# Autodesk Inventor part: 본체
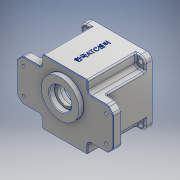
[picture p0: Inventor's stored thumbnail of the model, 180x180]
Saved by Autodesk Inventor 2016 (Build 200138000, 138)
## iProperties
Created: 2017-01
Part Number: 본체
Material: 알루미늄 6061
Document SubType Name: Modeling
Designer: Owner
Mass: 876.605 g
Surface Area: 765.17 cm^2
Volume: 324.669 cm^3
Density: 2.7 g/cm^3
Appearance: 알루미늄 - 평지
Author: Owner
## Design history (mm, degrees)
sketch "스케치1"
  geometry: L1 (47, -47)-(-47, -47); L2 (-47, -47)-(-47, 47); L3 (-47, 47)-(47, 47); L4 (47, 47)-(47, -47); L5 (47, -47)-(-47, 47); L6 (-47, -47)-(47, 47); 1 further point
  constraints: 12 end point, 2 midpoint, 2 parallel, 1 horizontal, 1 perpendicular
  dimensions: "d0" = 94 distance of L2.end L3.end; "d1" = 94 distance of L1.end L2.end
extrude "돌출1" new body sketch "스케치1" distance "d2" = 10; taper "d3" = 0 deg
sketch "스케치2"
  geometry: L1 (-33, -47)-(33, -47); L2 (33, 47)-(-33, 47); L3 (-33, -47)-(33, 47); L4 (33, -47)-(-33, 47); L5 (47, -30)-(47, 30); L6 (-47, 30)-(-47, -30); L7 (-47, -30)-(47, 30); L8 (47, -30)-(-47, 30); L9 (47, 30)-(33, 30); L10 (-33, 30)-(-47, 30); L11 (33, -47)-(33, -30); L12 (33, 30)-(33, 47); L13 (-33, 47)-(-33, 30); L14 (-33, -30)-(-33, -47); L15 (-47, -30)-(-33, -30); L16 (33, -30)-(47, -30); 9 further points
  constraints: 32 end point, 12 midpoint, 10 parallel, 4 perpendicular, 3 horizontal, 2 horizontal alignment, 2 vertical alignment
  dimensions: "d4" = 66 distance of L2.end L2.start; "d5" = 94 distance of L2.start L1.end; "d6" = 94 distance of L6.start L5.end; "d7" = 60 distance of L5.end L5.start
extrude "돌출2" join sketch "스케치2" distance "d8" = 70; taper "d9" = 0 deg
sketch "스케치3"
  geometry: L1 (70, -30)-(70, 30); L2 (-70, 30)-(-70, -30); L3 (-70, -30)-(70, 30); L4 (70, -30)-(-70, 30); L5 (33, -30)-(33, -47) reference; L6 (-33, 47)-(33, 47); L7 (33, -47)-(-33, -47); L8 (-33, 47)-(33, -47); L9 (33, 47)-(-33, -47); L10 (70, 30)-(33, 30); L11 (-33, 30)-(-70, 30); L12 (33, 47)-(33, 30); L13 (33, -30)-(33, -47); L14 (-70, -30)-(-33, -30); L15 (33, -30)-(70, -30); L16 (-33, -47)-(-33, -30); L17 (-33, 30)-(-33, 47); 9 further points
  constraints: 32 end point, 12 midpoint, 10 parallel, 4 perpendicular, 3 horizontal, 2 horizontal alignment, 2 vertical alignment
  dimensions: "d10" = 140 distance of L2.start L1.end; "d11" = 60 distance of L1.end L1.start
extrude "돌출3" join sketch "스케치3" distance "d12" = 13; taper "d13" = 0 deg
sketch "스케치5"
  geometry: 2 further points
  constraints: 1 coincident
hole "구멍1" sketch "스케치5" at (0, 0) diameter "d14" = 80; stored, may be unused: countersink angle "d18" = 90 deg, drill point angle "d20" = 0 deg; dims "d15" = 6, "d16" = 86, "d17" = 9, "d19" = 71
sketch "스케치6"
  geometry: C1 r 21 at (0, -11); 1 further point
  constraints: 1 centre point, 1 vertical alignment
  dimensions: "d21" = 42 diameter of C1; "d22" = 11 distance of point (0, 0) C1.centre
extrude "돌출4" join sketch "스케치6" distance "d23" = 7; taper "d24" = 0 deg
sketch "스케치7"
  geometry: C1 r 15 at (0, 20); 1 further point
  constraints: 1 centre point, 1 vertical alignment
  dimensions: "d25" = 30 diameter of C1; "d26" = 20 distance of point (0, 0) C1.centre
extrude "돌출5" join sketch "스케치7" distance "d27" = 7; taper "d28" = 0 deg
hole "구멍2" diameter "d31" = 35; stored, may be unused: countersink angle "d35" = 90 deg, drill point angle "d37" = 0 deg; dims "d29" = 10, "d30" = 10, "d32" = 6, "d33" = 86, "d34" = 9, "d36" = 10
hole "구멍3" diameter "d40" = 25; stored, may be unused: countersink angle "d44" = 90 deg, drill point angle "d46" = 0 deg; dims "d38" = 10, "d39" = 10, "d41" = 6, "d42" = 86, "d43" = 9, "d45" = 5
sketch "스케치8"
  geometry: C1 r 12.5 at (0, 11) reference; C2 r 17.5 at (0, 11) reference; C3 r 27.5 at (0, 11); 1 further point
  constraints: 1 centre point, 1 coincident
  dimensions: "d47" = 55 diameter of C3
extrude "돌출6" join sketch "스케치8" distance "d48" = 7; taper "d49" = 0 deg
hole "구멍4" diameter "d52" = 32; stored, may be unused: countersink angle "d56" = 90 deg, drill point angle "d58" = 0 deg; dims "d50" = 10, "d51" = 10, "d53" = 6, "d54" = 86, "d55" = 9, "d57" = 8
hole "구멍5" diameter "d61" = 22; stored, may be unused: countersink angle "d65" = 90 deg, drill point angle "d67" = 0 deg; dims "d62" = 6, "d63" = 86, "d64" = 9, "d66" = 7, "d77" = 10, "d78" = 10
hole "구멍6" diameter "d70" = 19; stored, may be unused: countersink angle "d74" = 90 deg, drill point angle "d76" = 0 deg; dims "d68" = 10, "d69" = 10, "d71" = 6, "d72" = 86, "d73" = 9, "d75" = 1
sketch "스케치13"
  geometry: L1 (-36, -4)-(-39.799, -4); L2 (-36, 4)-(-39.799, 4); C1 r 40 at (0, 0) reference; A1 r 4 centre (-36, 0) between (-36, -4) and (-36, 4); A2 r 40 centre (0, 0) between (-39.799, -4) and (-39.799, 4) reference; 1 further point
  constraints: 4 end point, 4 point on circle, 2 horizontal, 2 tangent, 1 centre point, 1 horizontal alignment
  dimensions: "d79" = 8 diameter of A1; "d80" = 36 distance of point (0, 0) A1.centre
extrude "돌출7" join sketch "스케치13" stored distance "d81" = 7; taper "d82" = 0 deg
chamfer "모따기1" distance "d86" = 8; stored, may be unused: second distance "d87" = 2, angle "d88" = 45 deg
fillet "모깎기1" dims "d89" = 5
fillet "모깎기2" dims "d90" = 5
fillet "모깎기3" dims "d91" = 8
sketch "스케치14"
  geometry: L1 (70, -19.929)-(70, 19.929) reference; 2 further points
  dimensions: "d101" = 19 vertical distance of point (0, 0) point (60, -19); "d102" = 10 distance from line of L1 point (60, -19)
hole "구멍8" sketch "스케치14" at (60, -19) diameter "d103" = 4; stored, may be unused: countersink angle "d107" = 90 deg, drill point angle "d109" = 0 deg; dims "d104" = 6, "d105" = 10, "d106" = 4, "d108" = 1
fillet "모깎기4" dims "d110" = 2
fillet "모깎기5" dims "d111" = 2
fillet "모깎기6" dims "d112" = 2
fillet "모깎기7" dims "d113" = 2
sketch "스케치16"
  geometry: L1 (-31, -47)-(31, -47) reference; L2 (33, -45)-(33, -35) reference; L3 (38, -30)-(59.929, -30) reference; L4 (68.536, -23.464)-(63.464, -28.536) reference; L5 (70, 19.929)-(70, -19.929) reference; L6 (63.464, 28.536)-(68.536, 23.464) reference; L7 (38, 30)-(59.929, 30) reference; L8 (33, 35)-(33, 45) reference; L9 (31, 47)-(-31, 47) reference; L10 (-33, 45)-(-33, 35) reference; L11 (-38, 30)-(-59.929, 30) reference; L12 (-68.536, 23.464)-(-63.464, 28.536) reference; L13 (-70, -19.929)-(-70, 19.929) reference; L14 (-63.464, -28.536)-(-68.536, -23.464) reference; L15 (-38, -30)-(-59.929, -30) reference; L16 (-33, -35)-(-33, -45) reference; L17 (-31, 46)-(31, 46); L18 (32, 45)-(32, 35); L19 (38, 29)-(59.929, 29); L20 (62.757, 27.828)-(67.828, 22.757); L21 (69, 19.929)-(69, -19.929); L22 (67.828, -22.757)-(62.757, -27.828); L23 (59.929, -29)-(38, -29); L24 (32, -35)-(32, -45); L25 (31, -46)-(-31, -46); L26 (-32, -45)-(-32, -35); L27 (-38, -29)-(-59.929, -29); L28 (-62.757, -27.828)-(-67.828, -22.757); L29 (-69, -19.929)-(-69, 19.929); L30 (-67.828, 22.757)-(-62.757, 27.828); L31 (-59.929, 29)-(-38, 29); L32 (-32, 35)-(-32, 45); C1 r 2 at (-60, -19) reference; C2 r 2 at (60, -19) reference; C3 r 2 at (-60, 19) reference; C4 r 2 at (60, 19) reference; C5 r 27.5 at (0, 11) reference; A1 r 2 centre (-31, -45) between (-33, -45) and (-31, -47) reference; A2 r 2 centre (31, -45) between (31, -47) and (33, -45) reference; A3 r 5 centre (38, -35) between (38, -30) and (33, -35) reference; A4 r 5 centre (59.929, -25) between (59.929, -30) and (63.464, -28.536) reference; A5 r 5 centre (65, -19.929) between (68.536, -23.464) and (70, -19.929) reference; A6 r 5 centre (65, 19.929) between (70, 19.929) and (68.536, 23.464) reference; A7 r 5 centre (59.929, 25) between (63.464, 28.536) and (59.929, 30) reference; A8 r 5 centre (38, 35) between (33, 35) and (38, 30) reference; A9 r 2 centre (31, 45) between (33, 45) and (31, 47) reference; A10 r 2 centre (-31, 45) between (-31, 47) and (-33, 45) reference; A11 r 5 centre (-38, 35) between (-38, 30) and (-33, 35) reference; A12 r 5 centre (-59.929, 25) between (-59.929, 30) and (-63.464, 28.536) reference; A13 r 5 centre (-65, 19.929) between (-68.536, 23.464) and (-70, 19.929) reference; A14 r 5 centre (-65, -19.929) between (-70, -19.929) and (-68.536, -23.464) reference; A15 r 5 centre (-59.929, -25) between (-63.464, -28.536) and (-59.929, -30) reference; A16 r 5 centre (-38, -35) between (-33, -35) and (-38, -30) reference; A17 r 1 centre (31, 45) between (32, 45) and (31, 46); A18 r 6 centre (38, 35) between (32, 35) and (38, 29); A19 r 4 centre (59.929, 25) between (62.757, 27.828) and (59.929, 29); A20 r 4 centre (65, 19.929) between (69, 19.929) and (67.828, 22.757); A21 r 4 centre (65, -19.929) between (67.828, -22.757) and (69, -19.929); A22 r 4 centre (59.929, -25) between (59.929, -29) and (62.757, -27.828); A23 r 6 centre (38, -35) between (38, -29) and (32, -35); A24 r 1 centre (31, -45) between (31, -46) and (32, -45); A25 r 1 centre (-31, -45) between (-32, -45) and (-31, -46); A26 r 6 centre (-38, -35) between (-32, -35) and (-38, -29); A27 r 4 centre (-59.929, -25) between (-62.757, -27.828) and (-59.929, -29); A28 r 4 centre (-65, -19.929) between (-69, -19.929) and (-67.828, -22.757); A29 r 4 centre (-65, 19.929) between (-67.828, 22.757) and (-69, 19.929); A30 r 4 centre (-59.929, 25) between (-59.929, 29) and (-62.757, 27.828); A31 r 6 centre (-38, 35) between (-38, 29) and (-32, 35); A32 r 1 centre (-31, 45) between (-31, 46) and (-32, 45); 1 further point
  constraints: 32 end point, 32 point on circle, 16 centre point, 31 other
  dimensions: "d114" = 1 distance between parallel lines of L9 L17
extrude "돌출8" cut sketch "스케치16" distance "d115" = 1; taper "d116" = 0 deg
chamfer "모따기2" distance "d117" = 1; stored, may be unused: second distance "d118" = 2, angle "d119" = 45 deg
fillet "모깎기8" dims "d120" = 0.3
fillet "모깎기9" dims "d121" = 0.3
hole "구멍9" diameter "d124" = 3.242; stored, may be unused: countersink angle "d128" = 90 deg, drill point angle "d130" = 118 deg; dims "d125" = 7, "d126" = 10, "d127" = 4, "d129" = 9, "d150" = 10, "d151" = 10
fillet "모깎기10" dims "d134" = 3
fillet "모깎기11" dims "d135" = 3.5
fillet "모깎기12" dims "d136" = 2
sketch "스케치17"
  geometry: 1 further point
fillet "모깎기13" dims "d137" = 1
sketch "스케치18"
  geometry: L1 (0, 0)-(78, 0) reference; 2 further points
  constraints: 1 vertical alignment, 1 other
  dimensions: "d138" = 40 distance from line of L1 point (39, -40)
feature "엠보싱1" sketch "스케치18" dims "d4" = 66, "d5" = 94, "d6" = 94, "d7" = 60, "d139" = 0.5, "d140" = 0
sketch "스케치19"
  geometry: 1 further point
sketch "스케치20"
  geometry: 2 further points
  dimensions: "d141" = 40 horizontal distance of point (0, 0) point (40, 40); "d142" = 40 horizontal distance of point (0, 0) point (40, 40)
hole "구멍10" sketch "스케치20" at (40, 40) diameter "d143" = 7; stored, may be unused: countersink angle "d147" = 90 deg, drill point angle "d149" = 118 deg; dims "d144" = 6, "d145" = 10, "d146" = 4, "d148" = 8
node "솔리드1"
pattern_circular "원형 패턴1" dims angle "d84" = 360 deg
mirror "대칭3"
mirror "대칭4"
pattern_circular "원형 패턴2" dims angle "d132" = 360 deg
mirror "대칭5"
mirror "대칭6"
node "투영된 루프1"
